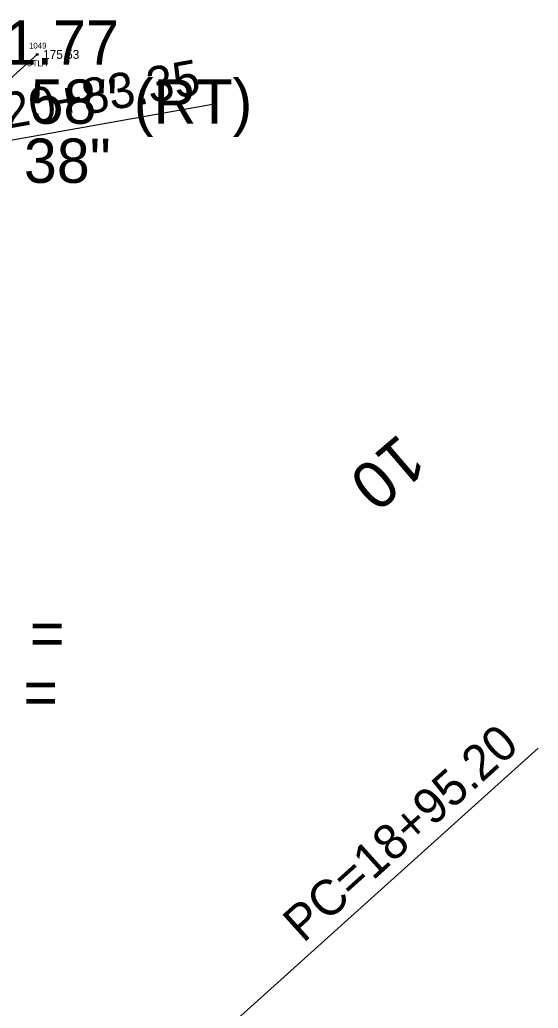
# Model space of a CAD drawing. Extents: x 1970735 to 1971583, y 794736 to 795766.
# Drawn here: x 1970900.8 to 1970988.6, y 795447.2 to 795614.6 of the extents above; entities that cross this region are included whole.
import ezdxf

# ---------------------------------------------------------------- set-up
doc = ezdxf.new("R2010")
doc.units = 0
for name, color, linetype in [('RD_EX_H2O', 7, 'Continuous'), ('RD_EX_H2O_txCode', 7, 'Continuous'), ('RD_EX_TX_H2O_ELEV', 7, 'Continuous'), ('RD_HC_Cl', 7, 'Continuous'), ('RD_HC_Data', 7, 'Continuous'), ('RD_HC_TX_Sta50', 7, 'Continuous'), ('RD_SMD_Locator', 7, 'Continuous')]:
    doc.layers.add(name, color=color, linetype=linetype)

msp = doc.modelspace()

# ---------------------------------------------------------------- linework, layer by layer
at = {"layer": 'RD_EX_H2O'}
msp.add_lwpolyline([(1970903.73, 795608.74), (1970856.44, 795566.14), (1970837.62, 795562.36), (1970831.66, 795579.46)], dxfattribs=at)
at = {"layer": 'RD_HC_Cl'}
msp.add_arc((1971153.66, 795639.87), 338.82, 190.1703, 221.9864, dxfattribs=at)
at = {"layer": 'RD_HC_Data'}
for p, q in [((1970820.17, 795580.04), (1970934.01, 795600.46)), ((1970901.81, 795413.21), (1970988.55, 795491.27))]:
    msp.add_line(p, q, dxfattribs=at)
at = {"layer": 'RD_SMD_Locator'}
msp.add_circle((1970903.73, 795608.74), 0.15, dxfattribs=at)

# ---------------------------------------------------------------- texts
at = {"layer": 'RD_EX_H2O_txCode'}
for s, p in [('1049', (1970902.34, 795609.74)), ('DTLA', (1970902, 795606.74))]:
    msp.add_text(s, height=1, dxfattribs=at).set_placement(p)
at = {"layer": 'RD_EX_TX_H2O_ELEV'}
msp.add_text('175.53', height=1.5, dxfattribs=at).set_placement((1970904.73, 795607.99))
at = {"layer": 'RD_HC_Data'}
for s, p in [('P.I. = 19+91.77', (1970849, 795607)), ('    = 31%%d 48\' 58" (RT)', (1970849, 795597)), ('D = 16%%d 54\' 38"', (1970849, 795587)), ('P.C. - LG% = ', (1970849, 795507)), ('P.T. - LG% = ', (1970849, 795497))]:
    msp.add_text(s, height=7.5, dxfattribs=at).set_placement(p)
for s, rotation, p in [('PT=20+83.35', 10.1703, (1970883.79, 795593.48)), ('PC=18+95.20', 41.9864, (1970948.79, 795458.18))]:
    msp.add_text(s, height=6, rotation=rotation, dxfattribs=at).set_placement(p)
at = {"layer": 'RD_HC_TX_Sta50'}
msp.add_text('10', height=8, rotation=220.5421, dxfattribs=at).set_placement((1970965.07, 795544.76))

doc.saveas('drawing.dxf')
